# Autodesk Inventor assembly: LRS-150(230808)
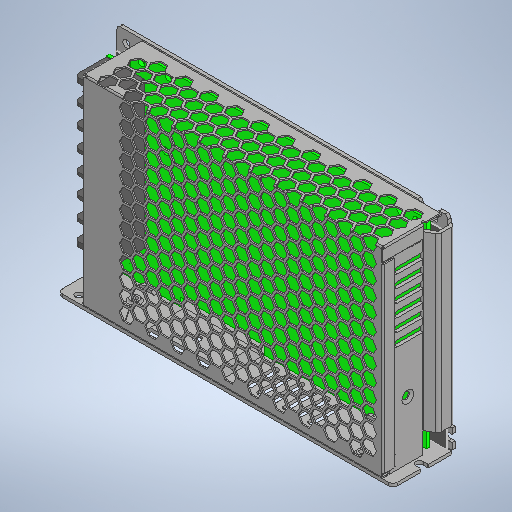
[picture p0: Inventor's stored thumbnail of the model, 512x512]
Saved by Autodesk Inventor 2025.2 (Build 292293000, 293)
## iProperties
Created: 2023-08
Part Number: LRS-150(230808)
Document SubType Name: Assembly
Designer: BennF
Title: LRS-150_ASM
Author: shalinice
Revision Number: 6LAST_VERSION
Sending System: CREO PARAMETRIC BY PTC INC, 2016390
Preprocessor: CREO PARAMETRIC BY PTC INC, 2016390
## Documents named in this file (3)
- C:\Users\BennF\Nextcloud\Benutzer\CNC JarBeRi\existing parts\Electronics\Powersupply LRS-150-24\LRS-150(230808)\LRS-150(230808)\LRS-150(230808).iam
- C:\Users\BennF\Nextcloud\Benutzer\CNC JarBeRi\existing parts\Electronics\Powersupply LRS-150-24\LRS-150(230808)\LRS-150(230808)\A2_ASM.iam
- C:\Users\BennF\Nextcloud\Benutzer\CNC JarBeRi\existing parts\Electronics\Powersupply LRS-150-24\LRS-150(230808)\LRS-150(230808)\MYLAR-1047790_ASM.iam
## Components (2 placed, 2 different names)
1. A2_ASM_28 [sub-assembly]
2. MYLAR-1047790_ASM_30 [sub-assembly]
